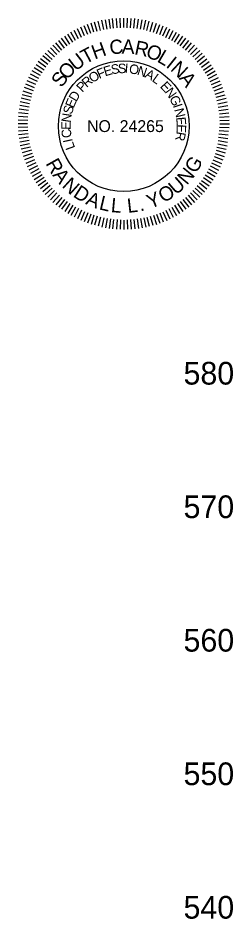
# Model space of a CAD drawing. Extents: x 1964850 to 1967424, y 1116563 to 1122204.
# Drawn here: x 1967341.4 to 1967421.9, y 1121425.5 to 1121762.9 of the extents above; entities that cross this region are included whole.
import ezdxf

# ---------------------------------------------------------------- set-up
doc = ezdxf.new("R2010")
doc.units = 0
doc.layers.add('RD_DDB_Profile_Elev', color=7, linetype='Continuous')
doc.layers.add('RD_TX_PEShield', color=7, linetype='Continuous')

msp = doc.modelspace()

# ---------------------------------------------------------------- linework, layer by layer
at = {"layer": 'RD_TX_PEShield'}
for p, q in [((1967369.86, 1121757.53), (1967368.76, 1121760.92)), ((1967369.86, 1121757.53), (1967368.76, 1121760.92)), ((1967371.08, 1121757.86), (1967370.1, 1121761.27)), ((1967371.08, 1121757.86), (1967370.1, 1121761.27)), ((1967372.29, 1121758.18), (1967371.43, 1121761.63)), ((1967372.29, 1121758.18), (1967371.43, 1121761.63)), ((1967373.51, 1121758.51), (1967372.77, 1121761.99)), ((1967373.51, 1121758.51), (1967372.77, 1121761.99)), ((1967374.75, 1121758.7), (1967374.13, 1121762.2)), ((1967374.75, 1121758.7), (1967374.13, 1121762.2)), ((1967375.99, 1121758.9), (1967375.5, 1121762.42)), ((1967375.99, 1121758.9), (1967375.5, 1121762.42)), ((1967377.23, 1121759.1), (1967376.86, 1121762.64)), ((1967377.23, 1121759.1), (1967376.86, 1121762.64)), ((1967378.49, 1121759.16), (1967378.24, 1121762.71)), ((1967378.49, 1121759.16), (1967378.24, 1121762.71)), ((1967379.74, 1121759.23), (1967379.62, 1121762.78)), ((1967379.74, 1121759.23), (1967379.62, 1121762.78)), ((1967381, 1121759.29), (1967381, 1121762.85)), ((1967381, 1121759.29), (1967381, 1121762.85)), ((1967382.26, 1121759.23), (1967382.38, 1121762.78)), ((1967382.26, 1121759.23), (1967382.38, 1121762.78)), ((1967383.51, 1121759.16), (1967383.76, 1121762.71)), ((1967383.51, 1121759.16), (1967383.76, 1121762.71)), ((1967384.77, 1121759.1), (1967385.14, 1121762.64)), ((1967384.77, 1121759.1), (1967385.14, 1121762.64)), ((1967386.01, 1121758.9), (1967386.51, 1121762.42)), ((1967386.01, 1121758.9), (1967386.51, 1121762.42)), ((1967387.25, 1121758.7), (1967387.87, 1121762.2)), ((1967387.25, 1121758.7), (1967387.87, 1121762.2)), ((1967388.49, 1121758.51), (1967389.23, 1121761.99)), ((1967388.49, 1121758.51), (1967389.23, 1121761.99)), ((1967388.49, 1121758.51), (1967389.23, 1121761.99)), ((1967389.71, 1121758.18), (1967390.57, 1121761.63)), ((1967389.71, 1121758.18), (1967390.57, 1121761.63)), ((1967389.71, 1121758.18), (1967390.57, 1121761.63)), ((1967390.92, 1121757.86), (1967391.9, 1121761.27)), ((1967390.92, 1121757.86), (1967391.9, 1121761.27)), ((1967390.92, 1121757.86), (1967391.9, 1121761.27)), ((1967392.14, 1121757.53), (1967393.24, 1121760.92)), ((1967392.14, 1121757.53), (1967393.24, 1121760.92)), ((1967392.14, 1121757.53), (1967393.24, 1121760.92)), ((1967362.98, 1121754.46), (1967361.2, 1121757.55)), ((1967362.98, 1121754.46), (1967361.2, 1121757.55)), ((1967364.1, 1121755.04), (1967362.43, 1121758.18)), ((1967364.1, 1121755.04), (1967362.43, 1121758.18)), ((1967365.22, 1121755.61), (1967363.66, 1121758.8)), ((1967365.22, 1121755.61), (1967363.66, 1121758.8)), ((1967366.34, 1121756.18), (1967364.89, 1121759.43)), ((1967366.34, 1121756.18), (1967364.89, 1121759.43)), ((1967367.51, 1121756.63), (1967366.18, 1121759.93)), ((1967367.51, 1121756.63), (1967366.18, 1121759.93)), ((1967368.69, 1121757.08), (1967367.47, 1121760.42)), ((1967368.69, 1121757.08), (1967367.47, 1121760.42)), ((1967393.31, 1121757.08), (1967394.53, 1121760.42)), ((1967393.31, 1121757.08), (1967394.53, 1121760.42)), ((1967393.31, 1121757.08), (1967394.53, 1121760.42)), ((1967394.49, 1121756.63), (1967395.82, 1121759.93)), ((1967394.49, 1121756.63), (1967395.82, 1121759.93)), ((1967394.49, 1121756.63), (1967395.82, 1121759.93)), ((1967395.66, 1121756.18), (1967397.11, 1121759.43)), ((1967395.66, 1121756.18), (1967397.11, 1121759.43)), ((1967395.66, 1121756.18), (1967397.11, 1121759.43)), ((1967396.78, 1121755.61), (1967398.34, 1121758.8)), ((1967396.78, 1121755.61), (1967398.34, 1121758.8)), ((1967396.78, 1121755.61), (1967398.34, 1121758.8)), ((1967397.9, 1121755.04), (1967399.57, 1121758.18)), ((1967397.9, 1121755.04), (1967399.57, 1121758.18)), ((1967397.9, 1121755.04), (1967399.57, 1121758.18)), ((1967399.02, 1121754.46), (1967400.8, 1121757.55)), ((1967399.02, 1121754.46), (1967400.8, 1121757.55)), ((1967399.02, 1121754.46), (1967400.8, 1121757.55)), ((1967358.84, 1121751.62), (1967356.65, 1121754.42)), ((1967358.84, 1121751.62), (1967356.65, 1121754.42)), ((1967359.81, 1121752.41), (1967357.72, 1121755.29)), ((1967359.81, 1121752.41), (1967357.72, 1121755.29)), ((1967360.87, 1121753.09), (1967358.88, 1121756.04)), ((1967360.87, 1121753.09), (1967358.88, 1121756.04)), ((1967361.92, 1121753.78), (1967360.04, 1121756.79)), ((1967361.92, 1121753.78), (1967360.04, 1121756.79)), ((1967400.08, 1121753.78), (1967401.96, 1121756.79)), ((1967400.08, 1121753.78), (1967401.96, 1121756.79)), ((1967400.08, 1121753.78), (1967401.96, 1121756.79)), ((1967401.13, 1121753.09), (1967403.12, 1121756.04)), ((1967401.13, 1121753.09), (1967403.12, 1121756.04)), ((1967401.13, 1121753.09), (1967403.12, 1121756.04)), ((1967402.19, 1121752.41), (1967404.28, 1121755.29)), ((1967402.19, 1121752.41), (1967404.28, 1121755.29)), ((1967402.19, 1121752.41), (1967404.28, 1121755.29)), ((1967403.16, 1121751.62), (1967405.35, 1121754.42)), ((1967403.16, 1121751.62), (1967405.35, 1121754.42)), ((1967403.16, 1121751.62), (1967405.35, 1121754.42)), ((1967355.1, 1121748.26), (1967352.55, 1121750.73)), ((1967355.1, 1121748.26), (1967352.55, 1121750.73)), ((1967355.99, 1121749.15), (1967353.52, 1121751.7)), ((1967355.99, 1121749.15), (1967353.52, 1121751.7)), ((1967356.88, 1121750.04), (1967354.5, 1121752.68)), ((1967356.88, 1121750.04), (1967354.5, 1121752.68)), ((1967357.86, 1121750.83), (1967355.57, 1121753.55)), ((1967357.86, 1121750.83), (1967355.57, 1121753.55)), ((1967404.14, 1121750.83), (1967406.43, 1121753.55)), ((1967404.14, 1121750.83), (1967406.43, 1121753.55)), ((1967404.14, 1121750.83), (1967406.43, 1121753.55)), ((1967405.12, 1121750.04), (1967407.5, 1121752.68)), ((1967405.12, 1121750.04), (1967407.5, 1121752.68)), ((1967405.12, 1121750.04), (1967407.5, 1121752.68)), ((1967406.01, 1121749.15), (1967408.48, 1121751.7)), ((1967406.01, 1121749.15), (1967408.48, 1121751.7)), ((1967406.01, 1121749.15), (1967408.48, 1121751.7)), ((1967406.9, 1121748.26), (1967409.46, 1121750.73)), ((1967406.9, 1121748.26), (1967409.46, 1121750.73)), ((1967406.9, 1121748.26), (1967409.46, 1121750.73)), ((1967352.63, 1121745.41), (1967349.83, 1121747.6)), ((1967352.63, 1121745.41), (1967349.83, 1121747.6)), ((1967353.42, 1121746.39), (1967350.7, 1121748.68)), ((1967353.42, 1121746.39), (1967350.7, 1121748.68)), ((1967354.21, 1121747.37), (1967351.57, 1121749.75)), ((1967354.21, 1121747.37), (1967351.57, 1121749.75)), ((1967407.79, 1121747.37), (1967410.43, 1121749.75)), ((1967407.79, 1121747.37), (1967410.43, 1121749.75)), ((1967407.79, 1121747.37), (1967410.43, 1121749.75)), ((1967408.58, 1121746.39), (1967411.3, 1121748.68)), ((1967408.58, 1121746.39), (1967411.3, 1121748.68)), ((1967408.58, 1121746.39), (1967411.3, 1121748.68)), ((1967409.37, 1121745.41), (1967412.17, 1121747.6)), ((1967409.37, 1121745.41), (1967412.17, 1121747.6)), ((1967409.37, 1121745.41), (1967412.17, 1121747.6)), ((1967350.47, 1121742.33), (1967347.45, 1121744.21)), ((1967350.47, 1121742.33), (1967347.45, 1121744.21)), ((1967351.15, 1121743.38), (1967348.21, 1121745.37)), ((1967351.15, 1121743.38), (1967348.21, 1121745.37)), ((1967351.84, 1121744.44), (1967348.96, 1121746.53)), ((1967351.84, 1121744.44), (1967348.96, 1121746.53)), ((1967410.16, 1121744.44), (1967413.04, 1121746.53)), ((1967410.16, 1121744.44), (1967413.04, 1121746.53)), ((1967410.16, 1121744.44), (1967413.04, 1121746.53)), ((1967410.85, 1121743.38), (1967413.79, 1121745.37)), ((1967410.85, 1121743.38), (1967413.79, 1121745.37)), ((1967410.85, 1121743.38), (1967413.79, 1121745.37)), ((1967411.53, 1121742.33), (1967414.55, 1121744.21)), ((1967411.53, 1121742.33), (1967414.55, 1121744.21)), ((1967411.53, 1121742.33), (1967414.55, 1121744.21)), ((1967348.64, 1121739.03), (1967345.45, 1121740.59)), ((1967348.64, 1121739.03), (1967345.45, 1121740.59)), ((1967349.21, 1121740.15), (1967346.07, 1121741.82)), ((1967349.21, 1121740.15), (1967346.07, 1121741.82)), ((1967349.78, 1121741.27), (1967346.7, 1121743.05)), ((1967349.78, 1121741.27), (1967346.7, 1121743.05)), ((1967412.22, 1121741.27), (1967415.3, 1121743.05)), ((1967412.22, 1121741.27), (1967415.3, 1121743.05)), ((1967412.22, 1121741.27), (1967415.3, 1121743.05)), ((1967412.79, 1121740.15), (1967415.93, 1121741.82)), ((1967412.79, 1121740.15), (1967415.93, 1121741.82)), ((1967412.79, 1121740.15), (1967415.93, 1121741.82)), ((1967413.36, 1121739.03), (1967416.55, 1121740.59)), ((1967413.36, 1121739.03), (1967416.55, 1121740.59)), ((1967413.36, 1121739.03), (1967416.55, 1121740.59)), ((1967347.62, 1121736.73), (1967344.32, 1121738.07)), ((1967347.62, 1121736.73), (1967344.32, 1121738.07)), ((1967348.07, 1121737.91), (1967344.82, 1121739.36)), ((1967348.07, 1121737.91), (1967344.82, 1121739.36)), ((1967413.93, 1121737.91), (1967417.18, 1121739.36)), ((1967413.93, 1121737.91), (1967417.18, 1121739.36)), ((1967413.93, 1121737.91), (1967417.18, 1121739.36)), ((1967414.38, 1121736.73), (1967417.68, 1121738.07)), ((1967414.38, 1121736.73), (1967417.68, 1121738.07)), ((1967414.38, 1121736.73), (1967417.68, 1121738.07)), ((1967346.39, 1121733.17), (1967342.98, 1121734.15)), ((1967346.39, 1121733.17), (1967342.98, 1121734.15)), ((1967346.72, 1121734.39), (1967343.33, 1121735.49)), ((1967346.72, 1121734.39), (1967343.33, 1121735.49)), ((1967347.17, 1121735.56), (1967343.83, 1121736.78)), ((1967347.17, 1121735.56), (1967343.83, 1121736.78)), ((1967414.83, 1121735.56), (1967418.17, 1121736.78)), ((1967414.83, 1121735.56), (1967418.17, 1121736.78)), ((1967414.83, 1121735.56), (1967418.17, 1121736.78)), ((1967415.28, 1121734.39), (1967418.67, 1121735.49)), ((1967415.28, 1121734.39), (1967418.67, 1121735.49)), ((1967415.28, 1121734.39), (1967418.67, 1121735.49)), ((1967415.61, 1121733.17), (1967419.02, 1121734.15)), ((1967415.61, 1121733.17), (1967419.02, 1121734.15)), ((1967415.61, 1121733.17), (1967419.02, 1121734.15)), ((1967345.74, 1121730.74), (1967342.26, 1121731.48)), ((1967345.74, 1121730.74), (1967342.26, 1121731.48)), ((1967346.07, 1121731.96), (1967342.62, 1121732.82)), ((1967346.07, 1121731.96), (1967342.62, 1121732.82)), ((1967415.93, 1121731.96), (1967419.38, 1121732.82)), ((1967415.93, 1121731.96), (1967419.38, 1121732.82)), ((1967415.93, 1121731.96), (1967419.38, 1121732.82)), ((1967416.26, 1121730.74), (1967419.74, 1121731.48)), ((1967416.26, 1121730.74), (1967419.74, 1121731.48)), ((1967416.26, 1121730.74), (1967419.74, 1121731.48)), ((1967345.15, 1121727.02), (1967341.61, 1121727.39)), ((1967345.15, 1121727.02), (1967341.61, 1121727.39)), ((1967345.35, 1121728.26), (1967341.83, 1121728.75)), ((1967345.35, 1121728.26), (1967341.83, 1121728.75)), ((1967345.55, 1121729.5), (1967342.04, 1121730.12)), ((1967345.55, 1121729.5), (1967342.04, 1121730.12)), ((1967416.45, 1121729.5), (1967419.96, 1121730.12)), ((1967416.45, 1121729.5), (1967419.96, 1121730.12)), ((1967416.45, 1121729.5), (1967419.96, 1121730.12)), ((1967416.65, 1121728.26), (1967420.17, 1121728.75)), ((1967416.65, 1121728.26), (1967420.17, 1121728.75)), ((1967416.65, 1121728.26), (1967420.17, 1121728.75)), ((1967416.85, 1121727.02), (1967420.39, 1121727.39)), ((1967416.85, 1121727.02), (1967420.39, 1121727.39)), ((1967416.85, 1121727.02), (1967420.39, 1121727.39)), ((1967345.02, 1121724.51), (1967341.47, 1121724.63)), ((1967345.02, 1121724.51), (1967341.47, 1121724.63)), ((1967345.09, 1121725.76), (1967341.54, 1121726.01)), ((1967345.09, 1121725.76), (1967341.54, 1121726.01)), ((1967416.91, 1121725.76), (1967420.46, 1121726.01)), ((1967416.91, 1121725.76), (1967420.46, 1121726.01)), ((1967416.91, 1121725.76), (1967420.46, 1121726.01)), ((1967416.98, 1121724.51), (1967420.53, 1121724.63)), ((1967416.98, 1121724.51), (1967420.53, 1121724.63)), ((1967416.98, 1121724.51), (1967420.53, 1121724.63)), ((1967344.96, 1121723.25), (1967341.4, 1121723.25)), ((1967344.96, 1121723.25), (1967341.4, 1121723.25)), ((1967345.02, 1121721.99), (1967341.47, 1121721.87)), ((1967345.02, 1121721.99), (1967341.47, 1121721.87)), ((1967345.09, 1121720.74), (1967341.54, 1121720.49)), ((1967345.09, 1121720.74), (1967341.54, 1121720.49)), ((1967416.78, 1121720.75), (1967420.32, 1121720.5)), ((1967416.78, 1121720.75), (1967420.32, 1121720.5)), ((1967416.91, 1121721.99), (1967420.46, 1121721.87)), ((1967416.91, 1121721.99), (1967420.46, 1121721.87)), ((1967417.05, 1121723.25), (1967420.61, 1121723.25)), ((1967417.05, 1121723.25), (1967420.61, 1121723.25)), ((1967417.05, 1121723.25), (1967420.61, 1121723.25)), ((1967345.15, 1121719.48), (1967341.61, 1121719.11)), ((1967345.15, 1121719.48), (1967341.61, 1121719.11)), ((1967345.35, 1121718.24), (1967341.83, 1121717.74)), ((1967345.35, 1121718.24), (1967341.83, 1121717.74)), ((1967345.55, 1121717), (1967342.04, 1121716.38)), ((1967345.55, 1121717), (1967342.04, 1121716.38)), ((1967416.39, 1121717.01), (1967419.88, 1121716.39)), ((1967416.39, 1121717.01), (1967419.88, 1121716.39)), ((1967416.52, 1121718.26), (1967420.03, 1121717.76)), ((1967416.52, 1121718.26), (1967420.03, 1121717.76)), ((1967416.65, 1121719.5), (1967420.17, 1121719.13)), ((1967416.65, 1121719.5), (1967420.17, 1121719.13)), ((1967345.74, 1121715.75), (1967342.26, 1121715.01)), ((1967345.74, 1121715.75), (1967342.26, 1121715.01)), ((1967346.07, 1121714.54), (1967342.62, 1121713.68)), ((1967346.07, 1121714.54), (1967342.62, 1121713.68)), ((1967415.93, 1121714.54), (1967419.38, 1121713.68)), ((1967415.93, 1121714.54), (1967419.38, 1121713.68)), ((1967416.26, 1121715.75), (1967419.74, 1121715.01)), ((1967416.26, 1121715.75), (1967419.74, 1121715.01)), ((1967346.39, 1121713.33), (1967342.98, 1121712.35)), ((1967346.39, 1121713.33), (1967342.98, 1121712.35)), ((1967346.72, 1121712.11), (1967343.33, 1121711.01)), ((1967347.17, 1121710.94), (1967343.83, 1121709.72)), ((1967347.17, 1121710.94), (1967343.83, 1121709.72)), ((1967414.83, 1121710.94), (1967418.17, 1121709.72)), ((1967414.83, 1121710.94), (1967418.17, 1121709.72)), ((1967415.28, 1121712.11), (1967418.67, 1121711.01)), ((1967415.28, 1121712.11), (1967418.67, 1121711.01)), ((1967415.61, 1121713.33), (1967419.02, 1121712.35)), ((1967415.61, 1121713.33), (1967419.02, 1121712.35)), ((1967347.62, 1121709.76), (1967344.32, 1121708.43)), ((1967347.62, 1121709.76), (1967344.32, 1121708.43)), ((1967348.07, 1121708.59), (1967344.82, 1121707.14)), ((1967348.07, 1121708.59), (1967344.82, 1121707.14)), ((1967348.64, 1121707.47), (1967345.45, 1121705.91)), ((1967348.64, 1121707.47), (1967345.45, 1121705.91)), ((1967413.36, 1121707.47), (1967416.55, 1121705.91)), ((1967413.36, 1121707.47), (1967416.55, 1121705.91)), ((1967413.93, 1121708.59), (1967417.18, 1121707.14)), ((1967413.93, 1121708.59), (1967417.18, 1121707.14)), ((1967414.38, 1121709.76), (1967417.68, 1121708.43)), ((1967414.38, 1121709.76), (1967417.68, 1121708.43)), ((1967349.21, 1121706.35), (1967346.07, 1121704.68)), ((1967349.21, 1121706.35), (1967346.07, 1121704.68)), ((1967349.78, 1121705.23), (1967346.7, 1121703.45)), ((1967349.78, 1121705.23), (1967346.7, 1121703.45)), ((1967350.47, 1121704.17), (1967347.45, 1121702.29)), ((1967350.47, 1121704.17), (1967347.45, 1121702.29)), ((1967411.53, 1121704.17), (1967414.55, 1121702.29)), ((1967411.53, 1121704.17), (1967414.55, 1121702.29)), ((1967412.22, 1121705.23), (1967415.3, 1121703.45)), ((1967412.22, 1121705.23), (1967415.3, 1121703.45)), ((1967412.79, 1121706.35), (1967415.93, 1121704.68)), ((1967412.79, 1121706.35), (1967415.93, 1121704.68)), ((1967351.15, 1121703.12), (1967348.21, 1121701.13)), ((1967351.15, 1121703.12), (1967348.21, 1121701.13)), ((1967351.84, 1121702.06), (1967348.96, 1121699.97)), ((1967351.84, 1121702.06), (1967348.96, 1121699.97)), ((1967352.63, 1121701.08), (1967349.83, 1121698.9)), ((1967352.63, 1121701.08), (1967349.83, 1121698.9)), ((1967353.42, 1121700.11), (1967350.7, 1121697.82)), ((1967353.42, 1121700.11), (1967350.7, 1121697.82)), ((1967408.58, 1121700.11), (1967411.3, 1121697.82)), ((1967408.58, 1121700.11), (1967411.3, 1121697.82)), ((1967409.37, 1121701.08), (1967412.17, 1121698.9)), ((1967409.37, 1121701.08), (1967412.17, 1121698.9)), ((1967410.16, 1121702.06), (1967413.04, 1121699.97)), ((1967410.16, 1121702.06), (1967413.04, 1121699.97)), ((1967410.85, 1121703.12), (1967413.79, 1121701.13)), ((1967410.85, 1121703.12), (1967413.79, 1121701.13)), ((1967354.21, 1121699.13), (1967351.57, 1121696.75)), ((1967354.21, 1121699.13), (1967351.57, 1121696.75)), ((1967355.1, 1121698.24), (1967352.55, 1121695.77)), ((1967355.1, 1121698.24), (1967352.55, 1121695.77)), ((1967355.99, 1121697.35), (1967353.52, 1121694.79)), ((1967355.99, 1121697.35), (1967353.52, 1121694.79)), ((1967406.01, 1121697.35), (1967408.48, 1121694.79)), ((1967406.01, 1121697.35), (1967408.48, 1121694.79)), ((1967406.9, 1121698.24), (1967409.46, 1121695.77)), ((1967406.9, 1121698.24), (1967409.46, 1121695.77)), ((1967407.79, 1121699.13), (1967410.43, 1121696.75)), ((1967407.79, 1121699.13), (1967410.43, 1121696.75)), ((1967356.88, 1121696.46), (1967354.5, 1121693.82)), ((1967356.88, 1121696.46), (1967354.5, 1121693.82)), ((1967357.86, 1121695.67), (1967355.57, 1121692.95)), ((1967357.86, 1121695.67), (1967355.57, 1121692.95)), ((1967358.84, 1121694.88), (1967356.65, 1121692.08)), ((1967358.84, 1121694.88), (1967356.65, 1121692.08)), ((1967359.81, 1121694.09), (1967357.72, 1121691.21)), ((1967359.81, 1121694.09), (1967357.72, 1121691.21)), ((1967360.87, 1121693.4), (1967358.88, 1121690.45)), ((1967360.87, 1121693.4), (1967358.88, 1121690.45)), ((1967401.13, 1121693.4), (1967403.12, 1121690.45)), ((1967401.13, 1121693.4), (1967403.12, 1121690.45)), ((1967402.19, 1121694.09), (1967404.28, 1121691.21)), ((1967402.19, 1121694.09), (1967404.28, 1121691.21)), ((1967403.16, 1121694.88), (1967405.35, 1121692.08)), ((1967403.16, 1121694.88), (1967405.35, 1121692.08)), ((1967404.14, 1121695.67), (1967406.43, 1121692.95)), ((1967404.14, 1121695.67), (1967406.43, 1121692.95)), ((1967405.12, 1121696.46), (1967407.5, 1121693.82)), ((1967361.92, 1121692.72), (1967360.04, 1121689.7)), ((1967361.92, 1121692.72), (1967360.04, 1121689.7)), ((1967362.98, 1121692.03), (1967361.2, 1121688.95)), ((1967362.98, 1121692.03), (1967361.2, 1121688.95)), ((1967364.1, 1121691.46), (1967362.43, 1121688.32)), ((1967364.1, 1121691.46), (1967362.43, 1121688.32)), ((1967365.22, 1121690.89), (1967363.66, 1121687.7)), ((1967365.22, 1121690.89), (1967363.66, 1121687.7)), ((1967366.34, 1121690.32), (1967364.89, 1121687.07)), ((1967366.34, 1121690.32), (1967364.89, 1121687.07)), ((1967395.66, 1121690.32), (1967397.11, 1121687.07)), ((1967395.66, 1121690.32), (1967397.11, 1121687.07)), ((1967396.78, 1121690.89), (1967398.34, 1121687.7)), ((1967396.78, 1121690.89), (1967398.34, 1121687.7)), ((1967397.9, 1121691.46), (1967399.57, 1121688.32)), ((1967397.9, 1121691.46), (1967399.57, 1121688.32)), ((1967399.02, 1121692.03), (1967400.8, 1121688.95)), ((1967399.02, 1121692.03), (1967400.8, 1121688.95)), ((1967400.08, 1121692.72), (1967401.96, 1121689.7)), ((1967400.08, 1121692.72), (1967401.96, 1121689.7)), ((1967367.51, 1121689.87), (1967366.18, 1121686.57)), ((1967367.51, 1121689.87), (1967366.18, 1121686.57)), ((1967368.69, 1121689.42), (1967367.47, 1121686.08)), ((1967368.69, 1121689.42), (1967367.47, 1121686.08)), ((1967369.86, 1121688.97), (1967368.76, 1121685.58)), ((1967369.86, 1121688.97), (1967368.76, 1121685.58)), ((1967371.08, 1121688.64), (1967370.1, 1121685.22)), ((1967371.08, 1121688.64), (1967370.1, 1121685.22)), ((1967372.29, 1121688.32), (1967371.43, 1121684.87)), ((1967372.29, 1121688.32), (1967371.43, 1121684.87)), ((1967373.51, 1121687.99), (1967372.77, 1121684.51)), ((1967373.51, 1121687.99), (1967372.77, 1121684.51)), ((1967374.75, 1121687.79), (1967374.13, 1121684.29)), ((1967374.75, 1121687.79), (1967374.13, 1121684.29)), ((1967375.99, 1121687.6), (1967375.5, 1121684.08)), ((1967375.99, 1121687.6), (1967375.5, 1121684.08)), ((1967377.23, 1121687.4), (1967376.86, 1121683.86)), ((1967377.23, 1121687.4), (1967376.86, 1121683.86)), ((1967378.49, 1121687.34), (1967378.24, 1121683.79)), ((1967378.49, 1121687.34), (1967378.24, 1121683.79)), ((1967379.74, 1121687.27), (1967379.62, 1121683.72)), ((1967379.74, 1121687.27), (1967379.62, 1121683.72)), ((1967381, 1121687.2), (1967381, 1121683.64)), ((1967381, 1121687.2), (1967381, 1121683.64)), ((1967382.26, 1121687.27), (1967382.38, 1121683.72)), ((1967382.26, 1121687.27), (1967382.38, 1121683.72)), ((1967383.51, 1121687.34), (1967383.76, 1121683.79)), ((1967383.51, 1121687.34), (1967383.76, 1121683.79)), ((1967384.77, 1121687.4), (1967385.14, 1121683.86)), ((1967384.77, 1121687.4), (1967385.14, 1121683.86)), ((1967386.01, 1121687.6), (1967386.51, 1121684.08)), ((1967386.01, 1121687.6), (1967386.51, 1121684.08)), ((1967387.25, 1121687.79), (1967387.87, 1121684.29)), ((1967387.25, 1121687.79), (1967387.87, 1121684.29)), ((1967388.49, 1121687.99), (1967389.23, 1121684.51)), ((1967388.49, 1121687.99), (1967389.23, 1121684.51)), ((1967389.71, 1121688.32), (1967390.57, 1121684.87)), ((1967389.71, 1121688.32), (1967390.57, 1121684.87)), ((1967390.92, 1121688.64), (1967391.9, 1121685.22)), ((1967390.92, 1121688.64), (1967391.9, 1121685.22)), ((1967392.14, 1121688.97), (1967393.24, 1121685.58)), ((1967392.14, 1121688.97), (1967393.24, 1121685.58)), ((1967393.31, 1121689.42), (1967394.53, 1121686.08)), ((1967393.31, 1121689.42), (1967394.53, 1121686.08)), ((1967394.49, 1121689.87), (1967395.82, 1121686.57)), ((1967394.49, 1121689.87), (1967395.82, 1121686.57))]:
    msp.add_line(p, q, dxfattribs=at)
msp.add_circle((1967381, 1121722.37), 24.48, dxfattribs=at)

# ---------------------------------------------------------------- texts
at = {"layer": 'RD_DDB_Profile_Elev'}
for s, p in [('580', (1967403.42, 1121625.58)), ('570', (1967403.42, 1121575.58)), ('560', (1967403.42, 1121525.58)), ('550', (1967403.42, 1121475.58)), ('540', (1967403.42, 1121425.58))]:
    msp.add_text(s, height=8.5, dxfattribs=at).set_placement(p)
at = {"layer": 'RD_TX_PEShield'}
for s, height, rotation, p in [('C', 5.34, 6.8832, (1967375.99, 1121749.11)), ('A', 5.34, 357.9448, (1967380.21, 1121749.56)), ('R', 5.34, 348.267, (1967384.79, 1121749.31)), ('T', 5.34, 28.0947, (1967366.66, 1121745.49)), ('H', 5.34, 19.9102, (1967370.1, 1121747.29)), ('O', 5.34, 339.3286, (1967388.93, 1121748.39)), ('L', 5.34, 329.6507, (1967393.19, 1121746.69)), ('U', 5.34, 37.7726, (1967362.98, 1121742.75)), ('I', 5.34, 321.4663, (1967396.53, 1121744.7)), ('O', 5.34, 47.4504, (1967359.81, 1121739.43)), ('F', 3.56, 23.0853, (1967371.81, 1121740.03)), ('E', 3.56, 16.1843, (1967374, 1121741)), ('S', 3.56, 8.6909, (1967376.49, 1121741.76)), ('S', 3.56, 1.79, (1967378.85, 1121742.16)), ('I', 3.56, 354.889, (1967381.24, 1121742.28)), ('O', 3.56, 350.4045, (1967382.8, 1121742.2)), ('N', 3.56, 341.7029, (1967385.78, 1121741.69)), ('N', 5.34, 317.0007, (1967398.22, 1121743.43)), ('S', 5.34, 54.9027, (1967357.78, 1121736.53)), ('R', 3.56, 39.8902, (1967367.1, 1121736.62)), ('O', 3.56, 31.7869, (1967369.24, 1121738.43)), ('A', 3.56, 333.0013, (1967388.65, 1121740.75)), ('L', 3.56, 324.2997, (1967391.34, 1121739.38)), ('A', 5.34, 307.3229, (1967401.52, 1121740.23)), ('P', 3.56, 46.7912, (1967365.49, 1121734.84)), ('E', 3.56, 313.2251, (1967394.41, 1121737.08)), ('D', 3.56, 59.074, (1967363.19, 1121731.26)), ('N', 3.56, 305.7317, (1967396.22, 1121735.2)), ('E', 3.56, 66.5674, (1967362.18, 1121728.86)), ('G', 3.56, 297.0301, (1967397.98, 1121732.75)), ('I', 3.56, 288.3285, (1967399.36, 1121730.06)), ('N', 3.56, 82.17, (1967361.13, 1121723.56)), ('S', 3.56, 73.4683, (1967361.54, 1121726.55)), ('N', 3.56, 283.8441, (1967399.9, 1121728.61)), ('E', 3.56, 89.6633, (1967361.14, 1121720.96)), ('E', 3.56, 275.1424, (1967400.63, 1121725.67)), ('C', 3.56, 97.7667, (1967361.54, 1121718.17)), ('E', 3.56, 267.6491, (1967400.89, 1121723.09)), ('I', 3.56, 102.2511, (1967361.93, 1121716.66)), ('R', 3.56, 260.1557, (1967400.82, 1121720.49)), ('L', 3.56, 109.7445, (1967362.84, 1121714.23)), ('R', 5.34, 299.1493, (1967351.6, 1121708.4)), ('G', 5.34, 60.1113, (1967408.11, 1121704.35)), ('N', 5.34, 50.4335, (1967404.69, 1121700.05)), ('A', 5.34, 308.0877, (1967354.13, 1121704)), ('U', 5.34, 40.7556, (1967400.6, 1121696.38)), ('N', 5.34, 317.7655, (1967357.6, 1121699.74)), ('D', 5.34, 327.4433, (1967361.73, 1121696.13)), ('A', 5.34, 337.1212, (1967366.42, 1121693.26)), ('Y', 5.34, 21.4, (1967390.88, 1121691.35)), ('O', 5.34, 31.0778, (1967395.96, 1121693.46)), ('L', 5.34, 346.799, (1967371.52, 1121691.23)), ('L', 5.34, 354.9835, (1967376.05, 1121690.2)), ('L', 5.34, 6.5171, (1967382.58, 1121689.86)), ('.', 5.34, 14.7016, (1967387.2, 1121690.41))]:
    msp.add_text(s, height=height, rotation=rotation, dxfattribs=at).set_placement(p)
msp.add_text('NO. 24265', height=4.45, dxfattribs=at).set_placement((1967367.25, 1121720.15))

doc.saveas('drawing.dxf')
